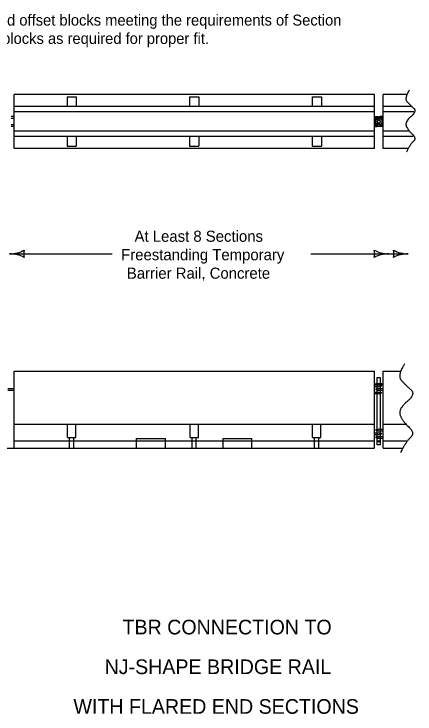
# Model space of a CAD drawing. Extents: x -2137026 to -2131464, y -2138478 to -2136524.
# Drawn here: x -2134666 to -2134120, y -2138478 to -2137522 of the extents above; entities that cross this region are included whole.
import ezdxf

# ---------------------------------------------------------------- set-up
doc = ezdxf.new("R2010")
doc.units = 0
for name, color, linetype in [('Level 2', 7, 'Continuous'), ('Level 3', 7, 'Continuous'), ('Level 41', 7, 'Continuous'), ('Level 9', 7, 'Continuous')]:
    doc.layers.add(name, color=color, linetype=linetype)

msp = doc.modelspace()

# ---------------------------------------------------------------- linework, layer by layer
at = {"layer": 'Level 2'}
for p, q in [((-2134174.91, -2137632.29), (-2134666.43, -2137632.29)), ((-2134666.43, -2137706.01), (-2134666.43, -2137632.29)), ((-2134174.91, -2137706.01), (-2134174.91, -2137632.29)), ((-2134130.31, -2137632.29), (-2134163.03, -2137632.29)), ((-2134163.03, -2137706.01), (-2134163.03, -2137632.29)), ((-2134174.91, -2137648.67), (-2134666.43, -2137648.67)), ((-2134174.91, -2137656.04), (-2134666.43, -2137656.04)), ((-2134123.82, -2137648.67), (-2134163.03, -2137648.67)), ((-2134120.89, -2137656.04), (-2134163.03, -2137656.04)), ((-2134174.91, -2137682.26), (-2134666.43, -2137682.26)), ((-2134126.79, -2137682.26), (-2134163.03, -2137682.26)), ((-2134174.91, -2137689.63), (-2134666.43, -2137689.63)), ((-2134121.79, -2137689.63), (-2134163.03, -2137689.63)), ((-2134174.91, -2137706.01), (-2134666.43, -2137706.01)), ((-2134128.73, -2137706.01), (-2134163.03, -2137706.01)), ((-2134672.37, -2137849.7), (-2134532.49, -2137849.7)), ((-2134261.47, -2137849.7), (-2134129.01, -2137849.7)), ((-2134666.43, -2138114.57), (-2134666.43, -2138009.96)), ((-2134666.43, -2138009.96), (-2134174.91, -2138009.96)), ((-2134174.91, -2138114.57), (-2134174.91, -2138009.96)), ((-2134163.03, -2138114.57), (-2134163.03, -2138009.96)), ((-2134163.03, -2138009.96), (-2134138.61, -2138009.96)), ((-2134666.43, -2138082.05), (-2134174.91, -2138082.05)), ((-2134163.03, -2138082.05), (-2134131.57, -2138082.05)), ((-2134666.43, -2138104.99), (-2134174.91, -2138104.99)), ((-2134499.31, -2138101.71), (-2134459.99, -2138101.71)), ((-2134499.31, -2138114.82), (-2134499.31, -2138104.99)), ((-2134459.99, -2138114.82), (-2134459.99, -2138104.99)), ((-2134381.35, -2138101.71), (-2134342.02, -2138101.71)), ((-2134381.35, -2138114.82), (-2134381.35, -2138104.99)), ((-2134342.02, -2138114.82), (-2134342.02, -2138104.99)), ((-2134163.03, -2138104.99), (-2134130.09, -2138104.99)), ((-2134666.18, -2138114.82), (-2134499.31, -2138114.82)), ((-2134459.99, -2138114.82), (-2134381.35, -2138114.82)), ((-2134342.02, -2138114.82), (-2134175.15, -2138114.82)), ((-2134162.78, -2138114.82), (-2134135.99, -2138114.82))]:
    msp.add_line(p, q, dxfattribs=at)
for centre, radius, start, end in [((-2134672.37, -2137807.2), 42.5, 270, 298.07249), ((-2134636.73, -2137849.7), 16.42, 162.26665, 197.73335), ((-2134190.77, -2137849.7), 16.42, 342.26665, 17.73335), ((-2134155.13, -2137807.2), 42.5, 241.92751, 270), ((-2134164.65, -2137849.7), 16.42, 342.26665, 17.73335), ((-2134129.01, -2137807.2), 42.5, 241.92751, 270), ((-2134672.37, -2137892.2), 42.5, 61.92751, 90), ((-2134155.13, -2137892.2), 42.5, 90, 118.07249), ((-2134129.01, -2137892.2), 42.5, 90, 118.07249)]:
    msp.add_arc(centre, radius, start, end, dxfattribs=at)
at = {"layer": 'Level 41'}
for p, q in [((-2134594.08, -2137635.41), (-2134581.49, -2137635.41)), ((-2134594.08, -2137635.41), (-2134594.08, -2137648.67)), ((-2134581.49, -2137635.41), (-2134581.49, -2137648.67)), ((-2134426.96, -2137635.41), (-2134414.38, -2137635.41)), ((-2134426.96, -2137635.41), (-2134426.96, -2137648.67)), ((-2134414.38, -2137635.41), (-2134414.38, -2137648.67)), ((-2134259.84, -2137635.41), (-2134259.84, -2137648.67)), ((-2134259.84, -2137635.41), (-2134247.26, -2137635.41)), ((-2134247.26, -2137635.41), (-2134247.26, -2137648.67)), ((-2134666.43, -2137662.47), (-2134670.36, -2137662.47)), ((-2134666.43, -2137664.82), (-2134670.36, -2137664.82)), ((-2134174.91, -2137662.47), (-2134170.98, -2137662.47)), ((-2134174.91, -2137664.82), (-2134170.98, -2137664.82)), ((-2134163.03, -2137662.47), (-2134166.96, -2137662.47)), ((-2134163.03, -2137664.82), (-2134166.96, -2137664.82)), ((-2134666.43, -2137673.48), (-2134670.36, -2137673.48)), ((-2134666.43, -2137675.83), (-2134670.36, -2137675.83)), ((-2134174.91, -2137673.48), (-2134170.98, -2137673.48)), ((-2134174.91, -2137675.83), (-2134170.98, -2137675.83)), ((-2134163.03, -2137673.48), (-2134166.96, -2137673.48)), ((-2134163.03, -2137675.83), (-2134166.96, -2137675.83)), ((-2134594.08, -2137689.63), (-2134594.08, -2137702.89)), ((-2134581.49, -2137689.63), (-2134581.49, -2137702.89)), ((-2134426.96, -2137689.63), (-2134426.96, -2137702.89)), ((-2134414.38, -2137689.63), (-2134414.38, -2137702.89)), ((-2134259.84, -2137689.63), (-2134259.84, -2137702.89)), ((-2134247.26, -2137689.63), (-2134247.26, -2137702.89)), ((-2134594.08, -2137702.89), (-2134581.49, -2137702.89)), ((-2134426.96, -2137702.89), (-2134414.38, -2137702.89)), ((-2134259.84, -2137702.89), (-2134247.26, -2137702.89)), ((-2134174.91, -2138028.56), (-2134166.41, -2138028.56)), ((-2134674.93, -2138033.48), (-2134666.43, -2138033.48)), ((-2134674.93, -2138035.6), (-2134666.43, -2138035.6)), ((-2134174.91, -2138030.68), (-2134166.41, -2138030.68)), ((-2134174.9, -2138038.39), (-2134166.41, -2138038.39)), ((-2134171.53, -2138033.48), (-2134163.03, -2138033.48)), ((-2134171.53, -2138035.6), (-2134163.03, -2138035.6)), ((-2134174.9, -2138040.51), (-2134166.41, -2138040.51)), ((-2134593.45, -2138100.62), (-2134593.45, -2138082.05)), ((-2134582.12, -2138100.62), (-2134582.12, -2138082.05)), ((-2134426.33, -2138100.62), (-2134426.33, -2138082.05)), ((-2134415.01, -2138100.62), (-2134415.01, -2138082.05)), ((-2134259.21, -2138100.62), (-2134259.21, -2138082.05)), ((-2134247.89, -2138100.62), (-2134247.89, -2138082.05)), ((-2134174.91, -2138094.1), (-2134166.41, -2138094.1)), ((-2134174.91, -2138096.22), (-2134166.41, -2138096.22)), ((-2134171.53, -2138089.18), (-2134163.04, -2138089.18)), ((-2134171.53, -2138091.31), (-2134163.04, -2138091.31)), ((-2134593.45, -2138100.62), (-2134582.12, -2138100.62)), ((-2134590.62, -2138114.82), (-2134590.62, -2138100.62)), ((-2134584.95, -2138114.82), (-2134584.95, -2138100.62)), ((-2134426.33, -2138100.62), (-2134415.01, -2138100.62)), ((-2134423.5, -2138114.82), (-2134423.5, -2138100.62)), ((-2134417.84, -2138114.82), (-2134417.84, -2138100.62)), ((-2134259.21, -2138100.62), (-2134247.89, -2138100.62)), ((-2134256.38, -2138114.82), (-2134256.38, -2138100.62)), ((-2134250.72, -2138114.82), (-2134250.72, -2138100.62)), ((-2134171.53, -2138099.01), (-2134163.04, -2138099.01)), ((-2134171.53, -2138101.14), (-2134163.04, -2138101.14))]:
    msp.add_line(p, q, dxfattribs=at)
for centre in [(-2134166.41, -2138029.62), (-2134171.53, -2138034.54), (-2134166.41, -2138039.45), (-2134171.53, -2138090.24), (-2134166.41, -2138095.16), (-2134171.53, -2138100.07)]:
    msp.add_circle(centre, 1.06, dxfattribs=at)
for centre, radius, start, end in [((-2134166.96, -2137669.15), 6.68, 90, 270), ((-2134166.96, -2137669.15), 4.33, 90, 270), ((-2134170.98, -2137669.15), 6.68, 270, 90), ((-2134170.98, -2137669.15), 4.33, 270, 90)]:
    msp.add_arc(centre, radius, start, end, dxfattribs=at)
at = {"layer": 'Level 9'}
for p, q in [((-2134173.06, -2137662.62), (-2134164.87, -2137662.62)), ((-2134173.06, -2137675.73), (-2134173.06, -2137662.62)), ((-2134164.87, -2137662.62), (-2134164.87, -2137675.73)), ((-2134164.87, -2137675.73), (-2134173.06, -2137675.73)), ((-2134171.02, -2138018.73), (-2134166.92, -2138018.73)), ((-2134171.02, -2138026.92), (-2134171.02, -2138018.73)), ((-2134166.92, -2138018.73), (-2134166.92, -2138026.92)), ((-2134173.06, -2138026.92), (-2134164.87, -2138026.92)), ((-2134173.06, -2138028.56), (-2134173.06, -2138026.92)), ((-2134164.87, -2138028.56), (-2134173.06, -2138028.56)), ((-2134171.02, -2138110.48), (-2134171.02, -2138028.56)), ((-2134166.92, -2138028.56), (-2134166.92, -2138110.48)), ((-2134164.87, -2138026.92), (-2134164.87, -2138028.56)), ((-2134499.31, -2138104.99), (-2134499.31, -2138101.71)), ((-2134499.31, -2138104.99), (-2134459.99, -2138104.99)), ((-2134459.99, -2138104.99), (-2134459.99, -2138101.71)), ((-2134381.35, -2138104.99), (-2134381.35, -2138101.71)), ((-2134381.35, -2138104.99), (-2134342.02, -2138104.99)), ((-2134342.02, -2138104.99), (-2134342.02, -2138101.71)), ((-2136987.54, -2138114.82), (-2134196.38, -2138114.82)), ((-2134666.43, -2138114.57), (-2134666.18, -2138114.82)), ((-2134175.15, -2138114.82), (-2134174.91, -2138114.57)), ((-2134166.92, -2138110.48), (-2134171.02, -2138110.48)), ((-2134163.03, -2138114.57), (-2134162.78, -2138114.82))]:
    msp.add_line(p, q, dxfattribs=at)
for centre, radius in [((-2134168.97, -2137669.17), 2.05), ((-2134168.97, -2138105.57), 1.02)]:
    msp.add_circle(centre, radius, dxfattribs=at)
for points in [[(-2134127.33, -2137626.55), (-2134134.61, -2137637.68), (-2134125.62, -2137647.1), (-2134116.63, -2137655.24), (-2134133.75, -2137669.8), (-2134129.04, -2137680.93), (-2134117.06, -2137692.06), (-2134126.47, -2137700.63), (-2134131.18, -2137710.9)], [(-2134133.79, -2138000.06), (-2134144.27, -2138016.09), (-2134131.33, -2138029.65), (-2134118.38, -2138041.37), (-2134143.04, -2138062.33), (-2134136.26, -2138078.36), (-2134119, -2138094.39), (-2134132.56, -2138106.72), (-2134139.34, -2138121.52)]]:
    msp.add_open_spline(points, degree=2, dxfattribs=at)

# ---------------------------------------------------------------- texts
at = {"layer": 'Level 3'}
for s, height, p in [('At Least 8 Sections', 15.2, (-2134502.02, -2137833.3)), ('Freestanding Temporary', 15.2, (-2134520.3, -2137858.5)), ('Barrier Rail, Concrete', 15.2, (-2134512.51, -2137883.7)), ('TBR CONNECTION TO', 20, (-2134518.44, -2138369.16)), ('NJ-SHAPE BRIDGE RAIL', 20, (-2134542.85, -2138423.33)), ('WITH FLARED END SECTIONS', 20, (-2134585.37, -2138477.51))]:
    msp.add_text(s, height=height, dxfattribs=at).set_placement(p)
at = {"layer": 'Level 9'}
for s, p in [('Furnish and install wood offset blocks meeting the requirements of Section ', (-2134881.04, -2137538.19)), ('4164. Field trim offset blocks as required for proper fit.', (-2134881.04, -2137563.19))]:
    msp.add_text(s, height=15, dxfattribs=at).set_placement(p)

doc.saveas('drawing.dxf')
